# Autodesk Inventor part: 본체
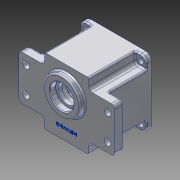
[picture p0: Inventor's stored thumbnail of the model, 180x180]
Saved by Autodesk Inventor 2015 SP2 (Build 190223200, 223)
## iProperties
Created: 2015-06
Part Number: 본체
Material: 알루미늄 6061
Document SubType Name: Modeling
Designer: AMC
Density: 2.7 g/cm^3
Appearance: 알루미늄 - 평지
Mass: 703.486 g
Surface Area: 672.192 cm^2
Volume: 260.55 cm^3
Author: AMC
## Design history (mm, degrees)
sketch "스케치1"
  geometry: L1 (-45, 45)-(45, 45); L2 (45, 45)-(45, -45); L3 (45, -45)-(-45, -45); L4 (-45, -45)-(-45, 45); 3 further points
  constraints: 8 end point, 2 midpoint, 2 parallel, 1 horizontal, 1 horizontal alignment, 1 perpendicular, 1 vertical alignment
  dimensions: "d0" = 90 distance of L1.start L1.end; "d1" = 90 distance of L3.end L1.start
extrude "돌출1" new body sketch "스케치1" distance "d2" = 70; taper "d3" = 0 deg
sketch "스케치2"
  geometry: L1 (45, 45)-(-45, 45) reference; L2 (-45, 45)-(-45, -45) reference; L3 (-45, -45)-(45, -45) reference; L4 (45, -45)-(45, 45) reference; L5 (-30, -65)-(30, -65); L6 (30, -65)-(30, 65); L7 (30, 65)-(-30, 65); L8 (-30, 65)-(-30, -65); 3 further points
  constraints: 8 end point, 2 midpoint, 2 parallel, 1 horizontal, 1 horizontal alignment, 1 perpendicular, 1 vertical alignment
  dimensions: "d4" = 130 distance of L5.end L6.end; "d5" = 60 distance of L6.end L7.end
extrude "돌출2" join sketch "스케치2" distance "d6" = 12; taper "d7" = 0 deg
sketch "스케치3"
  geometry: L1 (30, -45)-(45, -45) reference; L2 (45, -45)-(45, 45) reference; L3 (45, 45)-(30, 45) reference; L4 (30, 45)-(30, 65) reference; L5 (30, 65)-(-30, 65) reference; L6 (-30, 65)-(-30, 45) reference; L7 (-30, 45)-(-45, 45) reference; L8 (-45, 45)-(-45, -45) reference; L9 (-45, -45)-(-30, -45) reference; L10 (-30, -45)-(-30, -65) reference; L11 (-30, -65)-(30, -65) reference; L12 (30, -65)-(30, -45) reference; L13 (-45, -45)-(-30, -45); L14 (-30, -45)-(-30, -30); L15 (-30, -30)-(-45, -30); L16 (-45, -30)-(-45, -45); L17 (45, -45)-(30, -45); L18 (30, -45)-(30, -30); L19 (30, -30)-(45, -30); L20 (45, -30)-(45, -45); L21 (45, 45)-(30, 45); L22 (30, 45)-(30, 30); L23 (30, 30)-(45, 30); L24 (45, 30)-(45, 45); L25 (-45, 45)-(-30, 45); L26 (-30, 45)-(-30, 30); L27 (-30, 30)-(-45, 30); L28 (-45, 30)-(-45, 45); 1 further point
  constraints: 32 end point, 8 parallel, 4 horizontal, 4 perpendicular, 2 horizontal alignment, 2 vertical alignment
  dimensions: "d8" = 60 distance between parallel lines of L27 L15; "d9" = 15 distance of L13.end L14.end; "d10" = 60 distance between parallel lines of L22 L26; "d11" = 15 distance of L22.end L23.end
extrude "돌출3" cut sketch "스케치3" distance "d12" = 63; taper "d13" = 0 deg
sketch "스케치4"
  geometry: L1 (30, -45)-(-30, -45) reference; L2 (-30, 65)-(-30, 30) reference; L3 (-30, 30)-(-45, 30) reference; L4 (-45, 30)-(-45, -30) reference; L5 (-45, -30)-(-30, -30) reference; L6 (-30, -30)-(-30, -65) reference; L7 (-30, -65)-(30, -65) reference; L8 (30, -65)-(30, -30) reference; L9 (30, -30)-(45, -30) reference; L10 (45, -30)-(45, 30) reference; L11 (45, 30)-(30, 30) reference; L12 (30, 30)-(30, 65) reference; L13 (30, 65)-(-30, 65) reference; C1 r 25 at (11, 0); 1 further point
  constraints: 1 centre point, 1 horizontal alignment
  dimensions: "d14" = 50 diameter of C1; "d15" = 11 distance of point (0, 0) C1.centre
extrude "돌출4" join sketch "스케치4" distance "d16" = 7; taper "d17" = 0 deg
sketch "스케치5"
  geometry: 3 further points
  constraints: 2 coincident
hole "구멍1" sketch "스케치5" at (0, 0) diameter "d18" = 78; stored, may be unused: countersink angle "d22" = 90 deg, drill point angle "d24" = 0 deg; dims "d19" = 6, "d20" = 80, "d21" = 9, "d23" = 61
sketch "스케치6"
  geometry: C1 r 39 at (0, 0) reference; C2 r 25 at (-11, 0) reference; C3 r 20.5 at (-11, 0); 1 further point
  constraints: 1 centre point, 1 coincident
  dimensions: "d25" = 41 diameter of C3
extrude "돌출5" join sketch "스케치6" distance "d26" = 7; taper "d27" = 0 deg
hole "구멍2" diameter "d30" = 25; stored, may be unused: countersink angle "d34" = 90 deg, drill point angle "d36" = 0 deg; dims "d28" = 10, "d29" = 10, "d31" = 6, "d32" = 35, "d33" = 10, "d35" = 15
hole "구멍3" diameter "d39" = 32; stored, may be unused: countersink angle "d43" = 90 deg, drill point angle "d45" = 0 deg; dims "d37" = 10, "d38" = 10, "d40" = 6, "d41" = 35, "d42" = 10, "d44" = 8
sketch "스케치7"
  geometry: C1 r 39 at (0, 0) reference; A1 r 20.5 centre (-11, 0) between (8.117, 7.402) and (8.117, -7.402) reference; A2 r 14 centre (20, 0) between (8.117, -7.402) and (8.117, 7.402); 1 further point
  constraints: 4 point on circle, 1 centre point, 1 horizontal alignment
  dimensions: "d46" = 20 distance of A2.centre point (0, 0); "d47" = 28 diameter of A2
extrude "돌출6" join sketch "스케치7" distance "d48" = 7; taper "d49" = 0 deg
hole "구멍4" diameter "d52" = 19; stored, may be unused: countersink angle "d56" = 90 deg, drill point angle "d58" = 0 deg; dims "d50" = 10, "d51" = 10, "d53" = 6, "d54" = 22, "d55" = 7, "d57" = 8
sketch "스케치8"
  geometry: L1 (0, 0)-(-70.944, 0); L2 (0, 0)-(-50.344, 50.344); C1 r 39 at (0, 0) reference; A1 r 14 centre (20, 0) between (8.117, -7.402) and (8.117, 7.402) reference; A2 r 20.5 centre (-11, 0) between (8.117, 7.402) and (8.117, -7.402) reference; A3 r 35 centre (0, 0) between (-24.749, 24.749) and (-27.412, 21.762); A4 r 4 centre (-24.749, 24.749) between (-27.462, 21.809) and (-21.809, 27.462); A5 r 3.5 centre (-19.238, 29.836) between (-21.134, 32.777) and (-21.762, 27.412); A6 r 39 centre (0, 0) between (-32.777, 21.134) and (-21.134, 32.777) reference; A7 r 3.5 centre (-29.836, 19.238) between (-27.412, 21.762) and (-32.777, 21.134); 1 further point
  constraints: 13 point on circle, 4 centre point, 4 end point, 4 tangent, 1 coincident, 1 horizontal, 1 point on line
  dimensions: "d59" = 45 deg angle of L1 L2; "d60" = 70 diameter of A3; "d61" = 8 diameter of A4; "d62" = 7 diameter of A5; "d63" = 7 diameter of A7
extrude "돌출7" join sketch "스케치8" distance "d64" = 52; taper "d65" = 0 deg
hole "구멍5" diameter "d68" = 3.459; stored, may be unused: countersink angle "d72" = 90 deg, drill point angle "d74" = 118 deg; dims "d69" = 12, "d70" = 22, "d71" = 7, "d73" = 15, "d167" = 10, "d168" = 10
fillet "모깎기1" dims "d89" = 0.3
fillet "모깎기2" dims "d90" = 2
fillet "모깎기3" dims "d91" = 2
fillet "모깎기4" dims "d92" = 3
fillet "모깎기5" dims "d93" = 2
fillet "모깎기6" dims "d94" = 8
fillet "모깎기7" dims "d95" = 5
fillet "모깎기8" dims "d96" = 5
fillet "모깎기9" dims "d97" = 2
fillet "모깎기10" dims "d98" = 2
sketch "스케치10"
  geometry: L1 (43, 30)-(35, 30) reference; L2 (30, 35)-(30, 60) reference; L3 (25, 65)-(-25, 65) reference; L4 (-30, 60)-(-30, 35) reference; L5 (-35, 30)-(-43, 30) reference; L6 (-45, 28)-(-45, -28) reference; L7 (-43, -30)-(-35, -30) reference; L8 (-30, -35)-(-30, -60) reference; L9 (-25, -65)-(25, -65) reference; L10 (30, -60)-(30, -35) reference; L11 (35, -30)-(43, -30) reference; L12 (45, -28)-(45, 28) reference; C1 r 25 at (11, 0) reference; A1 r 37 centre (0, 0) between (-20.05, -31.096) and (20.05, -31.096) reference; A2 r 2 centre (43, 28) between (45, 28) and (43, 30) reference; A3 r 5 centre (35, 35) between (30, 35) and (35, 30) reference; A4 r 5 centre (25, 60) between (30, 60) and (25, 65) reference; A5 r 5 centre (-25, 60) between (-25, 65) and (-30, 60) reference; A6 r 5 centre (-35, 35) between (-35, 30) and (-30, 35) reference; A7 r 2 centre (-43, 28) between (-43, 30) and (-45, 28) reference; A8 r 2 centre (-43, -28) between (-45, -28) and (-43, -30) reference; A9 r 5 centre (-35, -35) between (-30, -35) and (-35, -30) reference; A10 r 5 centre (-25, -60) between (-30, -60) and (-25, -65) reference; A11 r 5 centre (25, -60) between (25, -65) and (30, -60) reference; A12 r 5 centre (35, -35) between (35, -30) and (30, -35) reference; A13 r 2 centre (43, -28) between (43, -30) and (45, -28) reference; 5 further points
  constraints: 2 horizontal alignment, 2 vertical alignment
  dimensions: "d99" = 35 distance of point (-17.5, -55) point (17.5, -55); "d100" = 12.5 distance from line of point (17.5, -55) L10; "d101" = 110 distance of point (17.5, -55) point (17.5, 55); "d102" = 10 distance from line of point (17.5, -55) L9
hole "구멍7" sketch "스케치10" at (17.5, -55), (-17.5, -55), (17.5, 55), (-17.5, 55) diameter "d103" = 9; stored, may be unused: countersink angle "d107" = 90 deg, drill point angle "d109" = 0 deg; dims "d104" = 12, "d105" = 22, "d106" = 7, "d108" = 15
hole "구멍8" diameter "d112" = 7; stored, may be unused: countersink angle "d116" = 90 deg, drill point angle "d118" = 0 deg; dims "d110" = 10, "d111" = 10, "d113" = 12, "d114" = 22, "d115" = 7, "d117" = 15
hole "구멍9" diameter "d121" = 7; stored, may be unused: countersink angle "d125" = 90 deg, drill point angle "d127" = 0 deg; dims "d119" = 10, "d120" = 10, "d122" = 12, "d123" = 22, "d124" = 7, "d126" = 15
hole "구멍10" diameter "d130" = 7; stored, may be unused: countersink angle "d134" = 90 deg, drill point angle "d136" = 0 deg; dims "d128" = 10, "d129" = 10, "d131" = 12, "d132" = 22, "d133" = 7, "d135" = 15
fillet "모깎기11" dims "d137" = 2
fillet "모깎기12" dims "d138" = 2
fillet "모깎기13" dims "d139" = 2
chamfer "모따기1" distance "d140" = 1; stored, may be unused: second distance "d141" = 2, angle "d142" = 45 deg
sketch "스케치11"
  geometry: L1 (-27.899, 14.518)-(-27.899, -14.518); L2 (-27.899, -14.518)-(-32.101, -14.518); L3 (-32.101, -14.518)-(-32.101, 14.518); L4 (-32.101, 14.518)-(-27.899, 14.518); L5 (-30, 14.518)-(-30, -14.518); L6 (-45, 28)-(-45, -28) reference; 2 further points
  constraints: 2 end point, 2 midpoint, 1 horizontal alignment, 2 other
  dimensions: "d143" = 15 distance between parallel lines of L5 L6
feature "엠보싱1" sketch "스케치11" dims "d144" = 0.5, "d145" = 0
fillet "모깎기14" dims "d146" = 2
fillet "모깎기15" dims "d147" = 2
hole "구멍11" diameter "d150" = 7; stored, may be unused: countersink angle "d154" = 90 deg, drill point angle "d156" = 118 deg; dims "d148" = 10, "d149" = 10, "d151" = 6, "d152" = 4, "d153" = 2, "d155" = 8
node "솔리드1"
pattern_circular "원형 패턴1" dims angle "d76" = 360 deg
node "투영된 루프1"
node "투영된 루프2"
node "투영된 루프3"
node "투영된 루프4"
node "투영된 루프5"
node "투영된 루프6"
node "투영된 루프8"
